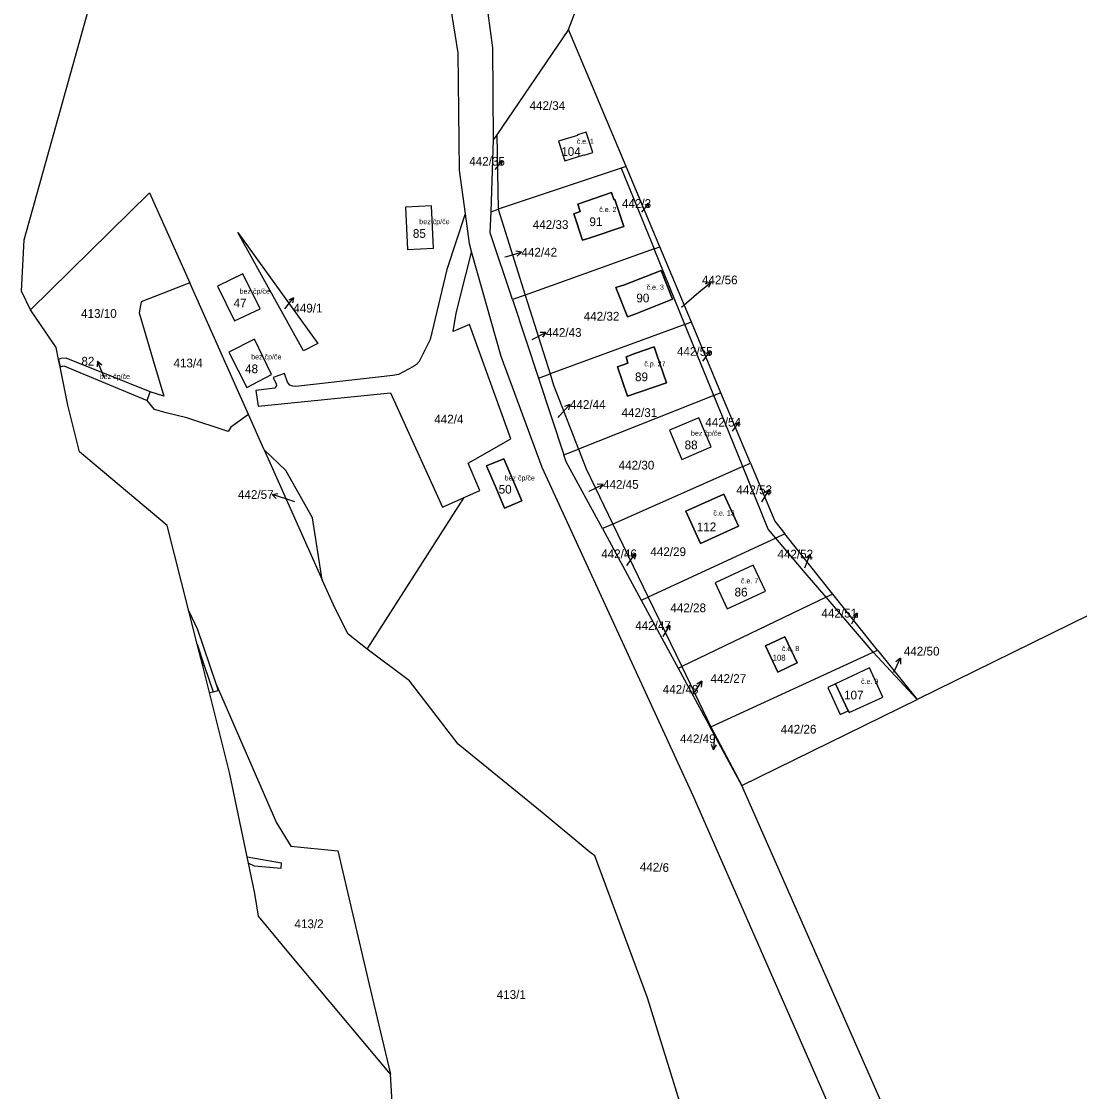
# Model space of a CAD drawing. Extents: x -887272 to -877616, y -1026687 to -1019819.
# Drawn here: x -880276 to -880069.6, y -1022983.7 to -1022775.2 of the extents above; entities that cross this region are included whole.
import ezdxf

# ---------------------------------------------------------------- set-up
doc = ezdxf.new("R2010")
doc.units = 0
for name, color, linetype in [('Definiční body', 7, 'Continuous'), ('Hranice parcel', 7, 'Continuous'), ('Parcelní čísla', 7, 'Continuous'), ('Polygon budovy', 7, 'Continuous'), ('Pop  PČ popisy', 7, 'Continuous'), ('Vnitřní kresba', 7, 'Continuous')]:
    doc.layers.add(name, color=color, linetype=linetype)

msp = doc.modelspace()

# ---------------------------------------------------------------- linework, layer by layer
at = {"layer": 'Hranice parcel'}
for p, q in [((-880169.29, -1022776.73), (-880144.75, -1022711.36)), ((-880169.29, -1022776.73), (-880183.31, -1022797.24)), ((-880158.09, -1022803.43), (-880169.29, -1022776.73)), ((-880184.42, -1022812.24), (-880183.96, -1022798.18)), ((-880183.31, -1022797.24), (-880183.96, -1022798.18)), ((-880183.31, -1022797.24), (-880183.01, -1022811.77)), ((-880159.04, -1022803.75), (-880183.01, -1022811.77)), ((-880158.09, -1022803.43), (-880159.04, -1022803.75)), ((-880159.04, -1022803.75), (-880152.64, -1022819.5)), ((-880151.52, -1022819.1), (-880158.09, -1022803.43)), ((-880184.42, -1022812.24), (-880183.01, -1022811.77)), ((-880183.01, -1022811.77), (-880177.75, -1022828.48)), ((-880152.64, -1022819.5), (-880177.75, -1022828.48)), ((-880152.64, -1022819.5), (-880151.52, -1022819.1)), ((-880146.65, -1022834.24), (-880152.64, -1022819.5)), ((-880145.36, -1022833.76), (-880151.52, -1022819.1)), ((-880231.71, -1022851.8), (-880243.18, -1022826.11)), ((-880177.75, -1022828.48), (-880180.24, -1022829.37)), ((-880180.24, -1022829.37), (-880175.17, -1022844.67)), ((-880177.75, -1022828.48), (-880172.9, -1022843.84)), ((-880146.65, -1022834.24), (-880172.9, -1022843.84)), ((-880145.36, -1022833.76), (-880146.65, -1022834.24)), ((-880139.58, -1022847.55), (-880145.36, -1022833.76)), ((-880268.45, -1022842.51), (-880268.76, -1022841.02)), ((-880268.45, -1022842.51), (-880268.76, -1022841.02)), ((-880266.96, -1022849.92), (-880268.45, -1022842.51)), ((-880266.96, -1022849.92), (-880268.45, -1022842.51)), ((-880175.17, -1022844.67), (-880172.9, -1022843.84)), ((-880175.17, -1022844.67), (-880170.2, -1022859.66)), ((-880251.46, -1022849.04), (-880250.87, -1022847.36)), ((-880250.06, -1022850.8), (-880251.46, -1022849.04)), ((-880248.22, -1022848.2), (-880250.87, -1022847.36)), ((-880140.96, -1022848.09), (-880167.35, -1022858.54)), ((-880139.58, -1022847.55), (-880140.96, -1022848.09)), ((-880133.84, -1022861.23), (-880139.58, -1022847.55)), ((-880228.66, -1022858.63), (-880231.71, -1022851.8)), ((-880228.66, -1022858.63), (-880217.33, -1022883.98)), ((-880170.2, -1022859.66), (-880167.35, -1022858.54)), ((-880135.34, -1022861.89), (-880133.84, -1022861.23)), ((-880135.34, -1022861.89), (-880160.66, -1022873.12)), ((-880208.55, -1022897.51), (-880189.68, -1022867.94)), ((-880243.35, -1022890.07), (-880247.56, -1022873.4)), ((-880243.35, -1022890.07), (-880247.56, -1022873.4)), ((-880160.66, -1022873.12), (-880162.69, -1022874.02)), ((-880162.69, -1022874.02), (-880155.12, -1022887.97)), ((-880160.66, -1022873.12), (-880153.78, -1022887.35)), ((-880128.89, -1022875.87), (-880153.78, -1022887.35)), ((-880127.1, -1022875.05), (-880128.89, -1022875.87)), ((-880117.76, -1022886.76), (-880127.1, -1022875.05)), ((-880155.12, -1022887.97), (-880153.78, -1022887.35)), ((-880155.12, -1022887.97), (-880147.92, -1022901.23)), ((-880153.78, -1022887.35), (-880147.24, -1022900.9)), ((-880119.08, -1022887.39), (-880147.24, -1022900.9)), ((-880117.76, -1022886.76), (-880119.08, -1022887.39)), ((-880109.91, -1022898.06), (-880119.08, -1022887.39)), ((-880109.04, -1022897.67), (-880117.76, -1022886.76)), ((-880200.32, -1022903.66), (-880208.55, -1022897.51)), ((-880141.57, -1022912.65), (-880109.91, -1022898.06)), ((-880109.91, -1022898.06), (-880109.04, -1022897.67)), ((-880101.32, -1022907.34), (-880109.91, -1022898.06)), ((-880109.04, -1022897.67), (-880101.32, -1022907.34)), ((-880147.92, -1022901.23), (-880147.24, -1022900.9)), ((-880147.24, -1022900.9), (-880141.57, -1022912.65)), ((-880147.92, -1022901.23), (-880141.69, -1022912.7)), ((-880135.5, -1022924.1), (-880101.32, -1022907.34)), ((-880141.69, -1022912.7), (-880141.57, -1022912.65)), ((-880135.5, -1022924.1), (-880141.69, -1022912.7)), ((-880141.57, -1022912.65), (-880135.5, -1022924.1)), ((-880231.98, -1022938.01), (-880235.4, -1022921.54)), ((-880231.98, -1022938.01), (-880235.4, -1022921.54)), ((-880204.04, -1022980.32), (-880223.5, -1022957.1)), ((-880204.04, -1022980.32), (-880223.5, -1022957.1))]:
    msp.add_line(p, q, dxfattribs=at)
for points in [[(-880275.46, -1022817.7), (-880256.82, -1022750.96), (-880251.78, -1022710.78), (-880245.5, -1022685.14), (-880239.72, -1022660.82), (-880229.65, -1022581.98)], [(-880275.46, -1022817.7), (-880256.82, -1022750.96), (-880251.78, -1022710.78), (-880245.5, -1022685.14), (-880239.72, -1022660.82), (-880229.65, -1022581.98)], [(-880192.42, -1022771.99), (-880190.9, -1022781.26), (-880190.62, -1022804.16), (-880189.48, -1022812.67), (-880193.03, -1022823.48), (-880196.3, -1022837.16), (-880198.41, -1022841.43), (-880198.93, -1022842.04), (-880199.51, -1022842.39), (-880202.49, -1022843.95), (-880203.58, -1022844.19), (-880222.49, -1022846.31), (-880223.07, -1022846.27), (-880223.68, -1022846.03), (-880224.08, -1022845.46), (-880224.72, -1022843.76), (-880226.91, -1022844.58), (-880226.29, -1022845.79), (-880226.25, -1022846.13), (-880226.55, -1022846.62), (-880230.28, -1022847.08), (-880229.81, -1022850.13), (-880204.01, -1022847.54), (-880193.87, -1022869.81), (-880189.68, -1022867.94)], [(-880183.96, -1022798.18), (-880184.04, -1022780.28), (-880184.98, -1022773.58)], [(-880171.28, -1022798.52), (-880170.05, -1022802.34), (-880166.3, -1022801.16), (-880166.29, -1022801.25), (-880164.56, -1022800.72), (-880165.85, -1022796.75), (-880167.58, -1022797.28), (-880167.54, -1022797.37), (-880171.28, -1022798.52)], [(-880274.2, -1022831.4), (-880251.03, -1022808.54), (-880243.18, -1022826.11)], [(-880160.92, -1022808.51), (-880160.45, -1022809.89), (-880160.31, -1022809.84), (-880158.51, -1022815.13), (-880165.3, -1022817.42), (-880166.57, -1022817.8), (-880168.26, -1022812.63), (-880167.04, -1022812.2), (-880167.52, -1022810.76), (-880160.92, -1022808.51)], [(-880196.03, -1022811.09), (-880201.13, -1022811.34), (-880200.74, -1022819.64), (-880195.63, -1022819.38), (-880196.03, -1022811.09)], [(-880180.24, -1022829.37), (-880184.56, -1022816.36), (-880184.42, -1022812.24)], [(-880274.2, -1022831.4), (-880276, -1022827.76), (-880275.46, -1022817.7)], [(-880274.2, -1022831.4), (-880276, -1022827.76), (-880275.46, -1022817.7)], [(-880218.2, -1022837.94), (-880220.97, -1022839.34), (-880233.79, -1022816.32), (-880218.2, -1022837.94)], [(-880189.68, -1022867.94), (-880186.63, -1022866.58), (-880188.91, -1022861.28), (-880180.55, -1022856.51), (-880188.62, -1022834.25), (-880191.78, -1022835.57), (-880191.23, -1022832.04), (-880189.34, -1022824.54), (-880188.21, -1022820.18), (-880182.52, -1022840.37), (-880174.52, -1022862.04), (-880144.98, -1022926.17), (-880115.13, -1022994.32), (-880103.69, -1023021.35), (-880083.68, -1023066.92)], [(-880160.09, -1022827.02), (-880158.41, -1022826.5), (-880151.22, -1022823.7), (-880149.01, -1022829.31), (-880156.16, -1022832.13), (-880157.81, -1022832.76), (-880160.09, -1022827.02)], [(-880243.18, -1022826.11), (-880252.64, -1022829.82), (-880253.02, -1022831.97), (-880250.46, -1022840.79), (-880248.22, -1022848.2)], [(-880229.43, -1022831.17), (-880232.82, -1022824.35), (-880237.77, -1022826.79), (-880234.44, -1022833.54), (-880229.43, -1022831.17)], [(-880268.76, -1022841.02), (-880269.22, -1022838.72), (-880274.2, -1022831.4)], [(-880268.76, -1022841.02), (-880269.22, -1022838.72), (-880274.2, -1022831.4)], [(-880140.96, -1022848.09), (-880145.48, -1022837.11), (-880146.65, -1022834.24)], [(-880227.25, -1022843.97), (-880230.53, -1022837.06), (-880235.53, -1022839.65), (-880232.03, -1022846.5), (-880227.25, -1022843.97)], [(-880158.1, -1022840.53), (-880156.21, -1022839.82), (-880152.58, -1022838.6), (-880152.15, -1022839.94), (-880150.22, -1022845.63), (-880157.78, -1022848.2), (-880159.74, -1022842.47), (-880157.73, -1022841.78), (-880158.1, -1022840.53)], [(-880250.87, -1022847.36), (-880267.24, -1022840.79), (-880268.34, -1022840.87), (-880268.76, -1022841.02)], [(-880268.45, -1022842.51), (-880267.74, -1022842.26), (-880251.46, -1022849.04)], [(-880172.9, -1022843.84), (-880172.21, -1022846.04), (-880167.35, -1022858.54)], [(-880135.34, -1022861.89), (-880138.84, -1022853.26), (-880140.96, -1022848.09)], [(-880247.56, -1022873.4), (-880264.64, -1022859.02), (-880266.96, -1022849.92)], [(-880247.56, -1022873.4), (-880264.64, -1022859.02), (-880266.96, -1022849.92)], [(-880231.71, -1022851.8), (-880235.16, -1022854.25), (-880235.69, -1022855.06), (-880243.75, -1022852.45), (-880247.77, -1022851.46), (-880250.06, -1022850.8)], [(-880147.22, -1022860.51), (-880141.52, -1022858.1), (-880143.93, -1022852.41), (-880149.63, -1022854.82), (-880147.22, -1022860.51)], [(-880217.33, -1022883.98), (-880219.24, -1022871.89), (-880224.43, -1022862.71), (-880228.66, -1022858.63)], [(-880167.35, -1022858.54), (-880165.86, -1022862.36), (-880160.66, -1022873.12)], [(-880183.21, -1022866.61), (-880185.28, -1022861.8), (-880181.92, -1022860.4), (-880178.39, -1022868.57), (-880181.77, -1022870.02), (-880183.21, -1022866.61)], [(-880162.69, -1022874.02), (-880169.75, -1022861.01), (-880170.2, -1022859.66)], [(-880133.84, -1022861.23), (-880129.07, -1022872.59), (-880127.1, -1022875.05)], [(-880128.89, -1022875.87), (-880130.37, -1022874.13), (-880135.34, -1022861.89)], [(-879968.62, -1022882.91), (-879973.51, -1022875.27), (-879993.92, -1022884.22), (-880013.19, -1022864.99), (-880049.16, -1022881.72), (-880101.32, -1022907.34)], [(-880136.17, -1022873.54), (-880143.6, -1022876.89), (-880146.43, -1022870.61), (-880139.04, -1022867.31), (-880136.17, -1022873.54)], [(-880119.08, -1022887.39), (-880123.18, -1022882.62), (-880128.89, -1022875.87)], [(-880130.91, -1022886.2), (-880133.29, -1022881.11), (-880140.74, -1022884.57), (-880138.39, -1022889.63), (-880130.91, -1022886.2)], [(-880208.55, -1022897.51), (-880212.25, -1022894.59), (-880214.82, -1022889.61), (-880217.33, -1022883.98)], [(-880243.35, -1022890.07), (-880241.64, -1022893.66), (-880238.09, -1022904.18), (-880237.6, -1022905.22), (-880226.25, -1022931.35), (-880223.43, -1022935.9), (-880214.29, -1022936.81), (-880207.9, -1022964), (-880204.04, -1022980.32)], [(-880235.4, -1022921.54), (-880239.33, -1022905.97), (-880240.65, -1022900.77), (-880241.72, -1022896.51), (-880243.35, -1022890.07)], [(-880235.4, -1022921.54), (-880239.33, -1022905.97), (-880240.65, -1022900.77), (-880241.72, -1022896.51), (-880243.35, -1022890.07)], [(-880128.5, -1022901.98), (-880130.87, -1022896.85), (-880127.15, -1022895.13), (-880124.75, -1022900.2), (-880128.5, -1022901.98)], [(-880114.77, -1022909.51), (-880114.61, -1022909.87), (-880108, -1022906.86), (-880110.64, -1022901.17), (-880117.26, -1022904.25), (-880118.77, -1022904.95), (-880116.35, -1022910.23), (-880114.77, -1022909.51)], [(-880129.04, -1023046.29), (-880129.43, -1023044.54), (-880130.69, -1023040.62), (-880137.84, -1023017.32), (-880138.66, -1023014.32), (-880144.53, -1022995.91), (-880145.04, -1022993.98), (-880153.89, -1022965.48), (-880164.21, -1022937.78), (-880165.13, -1022937.04), (-880174.46, -1022929.37), (-880190.85, -1022916.02), (-880200.32, -1022903.66)], [(-880100.73, -1023006.79), (-880107.25, -1022988.21), (-880135.5, -1022924.1)], [(-880223.5, -1022957.1), (-880229.78, -1022949.56), (-880230.5, -1022945.1), (-880231.72, -1022939.23), (-880231.98, -1022938.01)], [(-880223.5, -1022957.1), (-880229.78, -1022949.56), (-880230.5, -1022945.1), (-880231.72, -1022939.23), (-880231.98, -1022938.01)], [(-880188.9, -1023032.74), (-880202.24, -1023010.12), (-880204.04, -1022980.32)], [(-880188.9, -1023032.74), (-880202.24, -1023010.12), (-880204.04, -1022980.32)]]:
    msp.add_lwpolyline(points, dxfattribs=at)
at = {"layer": 'Polygon budovy'}
for points in [[(-880171.28, -1022798.52), (-880170.05, -1022802.34), (-880166.3, -1022801.16), (-880166.29, -1022801.25), (-880164.56, -1022800.72), (-880165.85, -1022796.75), (-880167.58, -1022797.28), (-880167.54, -1022797.37)], [(-880160.92, -1022808.51), (-880167.52, -1022810.76), (-880167.04, -1022812.2), (-880168.26, -1022812.63), (-880166.57, -1022817.8), (-880165.3, -1022817.42), (-880158.51, -1022815.13), (-880160.31, -1022809.84), (-880160.45, -1022809.89)], [(-880201.13, -1022811.34), (-880200.74, -1022819.64), (-880195.63, -1022819.38), (-880196.03, -1022811.09)], [(-880160.09, -1022827.02), (-880157.81, -1022832.76), (-880156.16, -1022832.13), (-880149.01, -1022829.31), (-880151.22, -1022823.7), (-880158.41, -1022826.5)], [(-880237.77, -1022826.79), (-880234.44, -1022833.54), (-880229.43, -1022831.17), (-880232.82, -1022824.35)], [(-880235.53, -1022839.65), (-880232.03, -1022846.5), (-880227.25, -1022843.97), (-880230.53, -1022837.06)], [(-880152.58, -1022838.6), (-880156.21, -1022839.82), (-880158.1, -1022840.53), (-880157.73, -1022841.78), (-880159.74, -1022842.47), (-880157.78, -1022848.2), (-880150.22, -1022845.63), (-880152.15, -1022839.94)], [(-880251.46, -1022849.04), (-880250.87, -1022847.36), (-880267.24, -1022840.79), (-880268.34, -1022840.87), (-880268.76, -1022841.02), (-880268.45, -1022842.51), (-880267.74, -1022842.26)], [(-880143.93, -1022852.41), (-880149.63, -1022854.82), (-880147.22, -1022860.51), (-880141.52, -1022858.1)], [(-880181.92, -1022860.4), (-880185.28, -1022861.8), (-880183.21, -1022866.61), (-880181.77, -1022870.02), (-880178.39, -1022868.57)], [(-880146.43, -1022870.61), (-880143.6, -1022876.89), (-880136.17, -1022873.54), (-880139.04, -1022867.31)], [(-880133.29, -1022881.11), (-880140.74, -1022884.57), (-880138.39, -1022889.63), (-880130.91, -1022886.2)], [(-880130.87, -1022896.85), (-880128.5, -1022901.98), (-880124.75, -1022900.2), (-880127.15, -1022895.13)], [(-880108, -1022906.86), (-880110.64, -1022901.17), (-880117.26, -1022904.25), (-880114.77, -1022909.51), (-880114.61, -1022909.87)]]:
    msp.add_lwpolyline(points, close=True, dxfattribs=at)
at = {"layer": 'Pop  PČ popisy'}
for p, q in [((-880183.62, -1022804.01), (-880182.27, -1022802.4)), ((-880182.27, -1022802.4), (-880182.99, -1022802.71)), ((-880182.27, -1022802.4), (-880182.45, -1022803.16)), ((-880155.03, -1022812.33), (-880153.67, -1022810.65)), ((-880153.67, -1022810.65), (-880154.4, -1022810.98)), ((-880153.67, -1022810.65), (-880153.84, -1022811.44)), ((-880181.74, -1022821.07), (-880181.37, -1022820.97)), ((-880181.37, -1022820.97), (-880178.48, -1022820.14)), ((-880178.48, -1022820.14), (-880179.59, -1022819.94)), ((-880178.48, -1022820.14), (-880179.31, -1022820.9)), ((-880143.89, -1022827.95), (-880141.59, -1022826.02)), ((-880141.59, -1022826.02), (-880142.68, -1022826.28)), ((-880141.59, -1022826.02), (-880142.04, -1022827.05)), ((-880147.31, -1022830.82), (-880143.89, -1022827.95)), ((-880224.6, -1022831.18), (-880222.97, -1022829.02)), ((-880222.97, -1022829.02), (-880223.88, -1022829.47)), ((-880222.97, -1022829.02), (-880223.16, -1022830.01)), ((-880176.4, -1022837.13), (-880173.73, -1022835.77)), ((-880173.73, -1022835.77), (-880174.85, -1022835.78)), ((-880173.73, -1022835.77), (-880174.39, -1022836.67)), ((-880176.4, -1022837.13), (-880176.41, -1022837.13)), ((-880143.11, -1022841.35), (-880141.7, -1022839.48)), ((-880141.7, -1022839.48), (-880142.48, -1022839.87)), ((-880141.7, -1022839.48), (-880141.86, -1022840.34)), ((-880261.14, -1022841.38), (-880261.21, -1022842.49)), ((-880259.97, -1022844.14), (-880261.14, -1022841.38)), ((-880261.14, -1022841.38), (-880260.29, -1022842.1)), ((-880259.72, -1022844.72), (-880259.97, -1022844.14)), ((-880171.05, -1022852.04), (-880169.04, -1022849.81)), ((-880169.04, -1022849.81), (-880170.08, -1022850.22)), ((-880169.04, -1022849.81), (-880169.34, -1022850.89)), ((-880171.35, -1022852.37), (-880171.05, -1022852.04)), ((-880137.31, -1022855), (-880136.06, -1022853.28)), ((-880136.06, -1022853.28), (-880136.76, -1022853.64)), ((-880136.06, -1022853.28), (-880136.19, -1022854.06)), ((-880165.28, -1022866.71), (-880162.58, -1022865.39)), ((-880162.58, -1022865.39), (-880163.7, -1022865.38)), ((-880162.58, -1022865.39), (-880163.26, -1022866.28)), ((-880227.12, -1022867.35), (-880226.02, -1022867.19)), ((-880224.27, -1022868.28), (-880227.12, -1022867.35)), ((-880227.12, -1022867.35), (-880226.33, -1022868.14)), ((-880165.35, -1022866.74), (-880165.28, -1022866.71)), ((-880131.61, -1022868.8), (-880130.19, -1022866.43)), ((-880130.19, -1022866.43), (-880131.06, -1022866.99)), ((-880130.19, -1022866.43), (-880130.27, -1022867.46)), ((-880222.71, -1022868.78), (-880224.27, -1022868.28)), ((-880157.91, -1022881.22), (-880156.29, -1022878.91)), ((-880156.29, -1022878.91), (-880157.22, -1022879.41)), ((-880156.29, -1022878.91), (-880156.45, -1022879.95)), ((-880123.25, -1022881.67), (-880122.16, -1022878.97)), ((-880122.16, -1022878.97), (-880122.97, -1022879.69)), ((-880122.16, -1022878.97), (-880122.07, -1022880.05)), ((-880114.04, -1022892.6), (-880113.05, -1022890.48)), ((-880113.05, -1022890.48), (-880113.73, -1022891.02)), ((-880113.05, -1022890.48), (-880113.03, -1022891.35)), ((-880150.87, -1022895.04), (-880149.57, -1022892.88)), ((-880149.57, -1022892.88), (-880150.36, -1022893.38)), ((-880149.57, -1022892.88), (-880149.64, -1022893.82)), ((-880105.9, -1022901.99), (-880104.58, -1022899.29)), ((-880104.58, -1022899.29), (-880105.47, -1022899.97)), ((-880104.58, -1022899.29), (-880104.57, -1022900.41)), ((-880144.94, -1022906.29), (-880143.31, -1022903.77)), ((-880143.31, -1022903.77), (-880144.27, -1022904.34)), ((-880143.31, -1022903.77), (-880143.43, -1022904.89)), ((-880140.86, -1022914.15), (-880141.02, -1022917.15)), ((-880141.02, -1022917.15), (-880141.46, -1022916.12)), ((-880141.02, -1022917.15), (-880140.46, -1022916.17))]:
    msp.add_line(p, q, dxfattribs=at)
at = {"layer": 'Vnitřní kresba'}
for p, q in [((-880189.48, -1022812.67), (-880188.7, -1022818.45)), ((-880188.7, -1022818.45), (-880188.21, -1022820.18)), ((-880241.72, -1022896.51), (-880240.35, -1022900.66)), ((-880240.65, -1022900.77), (-880240.35, -1022900.66)), ((-880240.35, -1022900.66), (-880238.62, -1022905.81)), ((-880238.09, -1022904.18), (-880237.62, -1022905.58)), ((-880114.77, -1022909.51), (-880117.26, -1022904.25)), ((-880239.33, -1022905.97), (-880238.62, -1022905.81)), ((-880238.62, -1022905.81), (-880237.62, -1022905.58)), ((-880231.98, -1022938.01), (-880225.26, -1022939.18)), ((-880231.72, -1022939.23), (-880230.6, -1022939.75)), ((-880230.6, -1022939.75), (-880225.34, -1022940.18)), ((-880225.34, -1022940.18), (-880225.26, -1022939.18))]:
    msp.add_line(p, q, dxfattribs=at)

# ---------------------------------------------------------------- texts
at = {"layer": 'Definiční body'}
for s, p in [('č.e. 1', (-880167.72, -1022799.01)), ('č.e. 2', (-880163.33, -1022812.31)), ('bez čp/če', (-880198.4, -1022814.68)), ('bez čp/če', (-880233.45, -1022828.25)), ('č.e. 3', (-880154.09, -1022827.45)), ('bez čp/če', (-880231.2, -1022841.03)), ('č.p. 27', (-880154.54, -1022842.39)), ('bez čp/če', (-880260.73, -1022844.85)), ('bez čp/če', (-880145.43, -1022855.92)), ('bez čp/če', (-880181.78, -1022864.63)), ('č.e. 13', (-880141.06, -1022871.46)), ('č.e. 7', (-880135.69, -1022884.69)), ('č.e. 8', (-880127.71, -1022897.87)), ('č.e. 9', (-880112.27, -1022904.27))]:
    msp.add_text(s, height=1, dxfattribs=at).set_placement(p)
at = {"layer": 'Parcelní čísla'}
for s, height, p in [('442/34', 1.7, (-880176.91, -1022792.42)), ('104', 1.7, (-880170.72, -1022801.37)), ('442/35', 1.7, (-880188.67, -1022803.27)), ('442/3', 1.7, (-880158.89, -1022811.5)), ('91', 1.7, (-880165.23, -1022815.05)), ('85', 1.7, (-880199.66, -1022817.34)), ('442/33', 1.7, (-880176.28, -1022815.61)), ('442/42', 1.7, (-880178.49, -1022820.99)), ('442/56', 1.7, (-880143.29, -1022826.39)), ('90', 1.7, (-880156.08, -1022829.91)), ('47', 1.7, (-880234.63, -1022830.91)), ('449/1', 1.7, (-880222.97, -1022831.89)), ('413/10', 1.7, (-880264.36, -1022832.93)), ('442/32', 1.7, (-880166.34, -1022833.47)), ('442/43', 1.7, (-880173.72, -1022836.63)), ('442/55', 1.7, (-880148.16, -1022840.33)), ('82', 1.7, (-880264.3, -1022842.24)), ('413/4', 1.7, (-880246.34, -1022842.59)), ('48', 1.7, (-880232.38, -1022843.72)), ('89', 1.7, (-880156.34, -1022845.28)), ('442/44', 1.7, (-880169.03, -1022850.67)), ('442/31', 1.7, (-880158.97, -1022852.25)), ('442/4', 1.7, (-880195.49, -1022853.52)), ('442/54', 1.7, (-880142.63, -1022854.13)), ('88', 1.7, (-880146.67, -1022858.55)), ('442/30', 1.7, (-880159.53, -1022862.49)), ('50', 1.7, (-880182.93, -1022867.19)), ('442/45', 1.7, (-880162.58, -1022866.25)), ('442/53', 1.7, (-880136.58, -1022867.3)), ('442/57', 1.7, (-880233.77, -1022868.22)), ('112', 1.7, (-880144.3, -1022874.52)), ('442/46', 1.7, (-880162.93, -1022879.77)), ('442/29', 1.7, (-880153.35, -1022879.36)), ('442/52', 1.7, (-880128.56, -1022879.82)), ('86', 1.7, (-880136.93, -1022887.24)), ('442/28', 1.7, (-880149.45, -1022890.3)), ('442/51', 1.7, (-880119.99, -1022891.34)), ('442/47', 1.7, (-880156.3, -1022893.75)), ('442/50', 1.7, (-880103.92, -1022898.75)), ('108', 1.139, (-880129.52, -1022899.74)), ('442/27', 1.7, (-880141.61, -1022904.08)), ('442/48', 1.7, (-880150.93, -1022906.18)), ('107', 1.7, (-880115.58, -1022907.3)), ('442/26', 1.7, (-880127.92, -1022913.96)), ('442/49', 1.7, (-880147.57, -1022915.82)), ('413/2', 1.7, (-880222.75, -1022951.88)), ('413/1', 1.7, (-880183.31, -1022965.68))]:
    msp.add_text(s, height=height, dxfattribs=at).set_placement(p)
msp.add_text('442/6', height=1.7, rotation=358, dxfattribs=at).set_placement((-880155.42, -1022940.75))

doc.saveas('drawing.dxf')
